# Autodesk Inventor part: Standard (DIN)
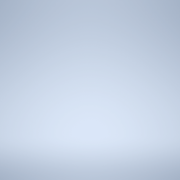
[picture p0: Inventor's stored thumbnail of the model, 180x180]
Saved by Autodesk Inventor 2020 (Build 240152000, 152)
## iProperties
Created: 2019-02
Part Number: Standard (DIN)
Material: Ogólny
Document SubType Name: Modeling
Density: 1 g/cm^3
Appearance: Domyślna
Manager: www.cadconsulting.pl
Company: Fabian Stasiak CAD Consulting
Subject: Zbiór ćwiczeń. Autodesk Inventor 2020. Kurs podstawowy
Author: F.Stasiak
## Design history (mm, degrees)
